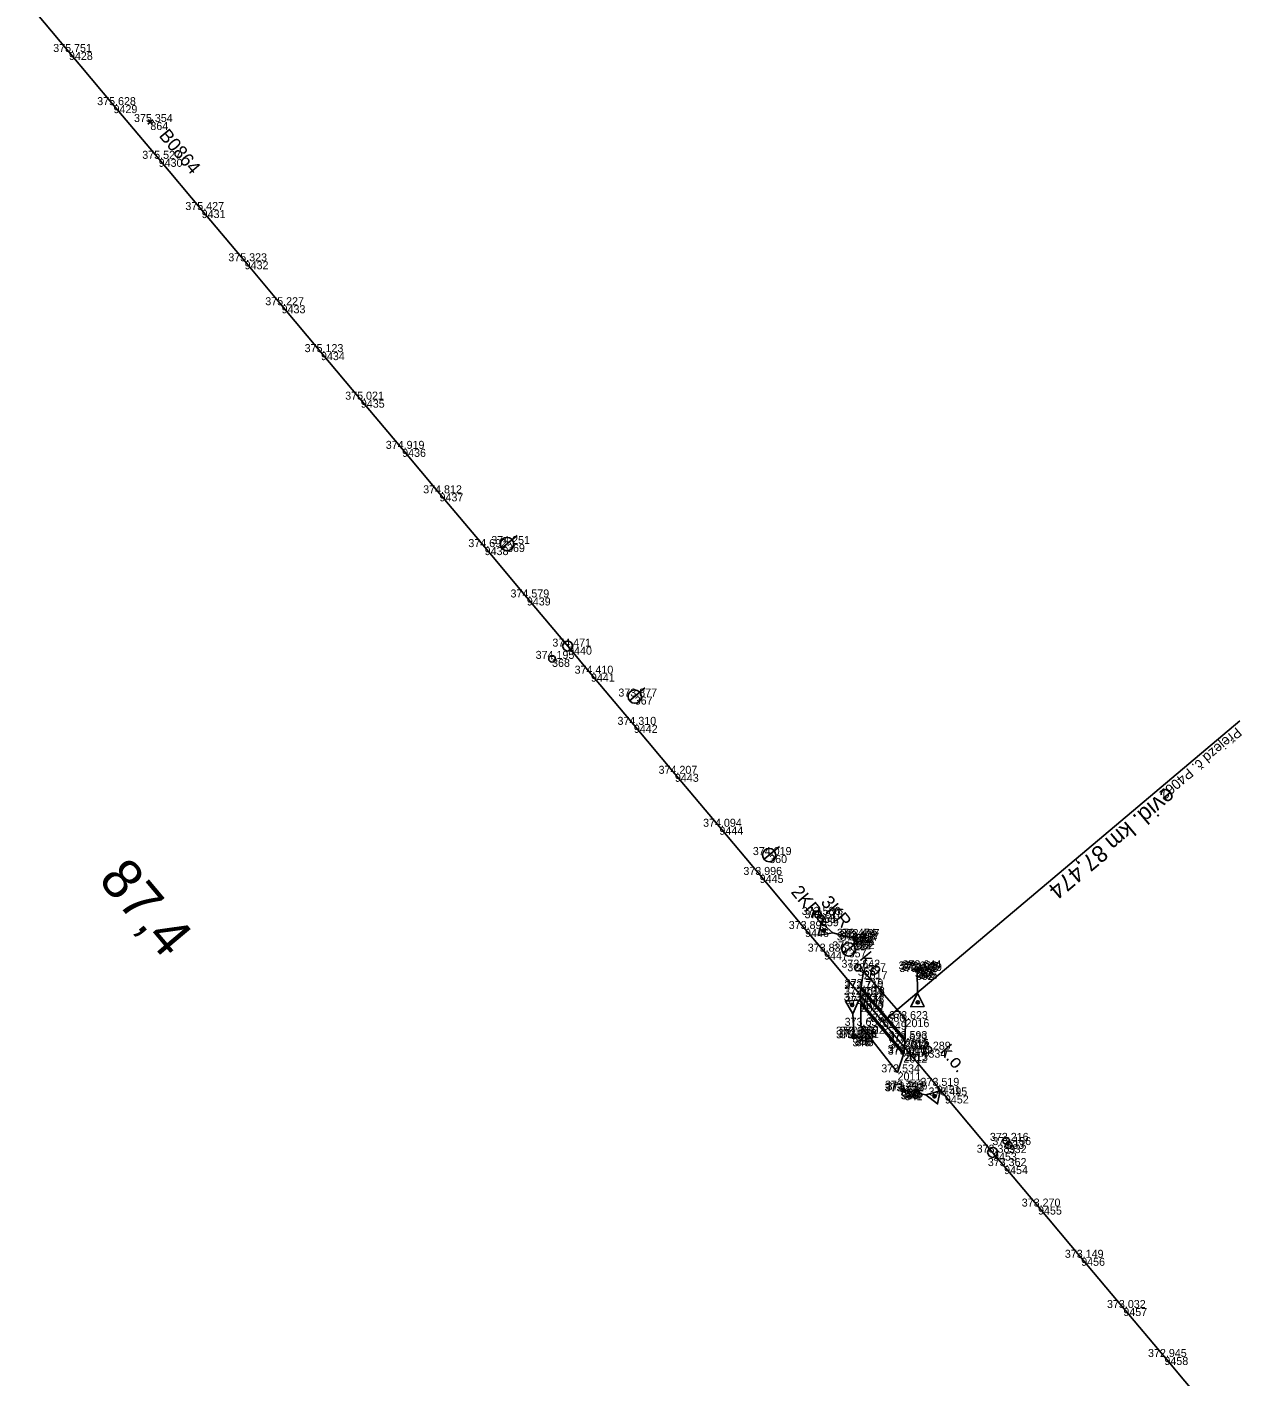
# Model space of a CAD drawing. Extents: x -599511 to -595511, y -1067427 to -1062061.
# Drawn here: x -596648.2 to -596466.1, y -1065676.3 to -1065474 of the extents above; entities that cross this region are included whole.
import ezdxf

# ---------------------------------------------------------------- set-up
doc = ezdxf.new("R2010")
doc.units = 0
for name, color, linetype in [('Vrstva 1', 7, 'Continuous'), ('Vrstva 12', 7, 'Continuous'), ('Vrstva 27', 7, 'Continuous'), ('Vrstva 4', 7, 'Continuous'), ('Vrstva 43', 7, 'Continuous'), ('Vrstva 50', 7, 'Continuous'), ('Vrstva 60', 7, 'Continuous'), ('Vrstva 61', 7, 'Continuous'), ('Vrstva 7', 7, 'Continuous')]:
    doc.layers.add(name, color=color, linetype=linetype)

msp = doc.modelspace()

# ---------------------------------------------------------------- linework, layer by layer
at = {"layer": 'Vrstva 1'}
msp.add_lwpolyline([(-596648.21, -1065470.29), (-596641.92, -1065477.78), (-596635.24, -1065485.75), (-596628.47, -1065493.8), (-596622.02, -1065501.48), (-596615.58, -1065509.16), (-596610.04, -1065515.75), (-596604.14, -1065522.78), (-596598.16, -1065529.91), (-596591.97, -1065537.28), (-596586.37, -1065543.95), (-596579.6, -1065552.01), (-596573.28, -1065559.56), (-596567.09, -1065566.93), (-596563.67, -1065570.99), (-596557.24, -1065578.66), (-596551.08, -1065586), (-596544.41, -1065593.94), (-596538.37, -1065601.16), (-596531.57, -1065609.27), (-596528.72, -1065612.66), (-596523.26, -1065619.18), (-596519.9, -1065623.17), (-596516.48, -1065627.21), (-596511.81, -1065632.78), (-596510.61, -1065634.22), (-596503.4, -1065642.8), (-596501.73, -1065644.81), (-596496.64, -1065650.88), (-596490.18, -1065658.56), (-596483.86, -1065666.09), (-596477.7, -1065673.43), (-596471.6, -1065680.69)], dxfattribs=at)
at = {"layer": 'Vrstva 12'}
for p, q in [((-596524.48, -1065625.11), (-596524.48, -1065625.11)), ((-596524.48, -1065625.65), (-596524.48, -1065625.65)), ((-596517.14, -1065633.2), (-596517.14, -1065633.2)), ((-596517.21, -1065633.58), (-596517.22, -1065633.59)), ((-596516.63, -1065633.73), (-596516.63, -1065633.73)), ((-596516.55, -1065633.33), (-596516.55, -1065633.33))]:
    msp.add_line(p, q, dxfattribs=at)
for points in [[(-596524.34, -1065610.43), (-596524.36, -1065610.97), (-596523.83, -1065611.03), (-596523.78, -1065610.48)], [(-596515.1, -1065615.33), (-596514.51, -1065615.16), (-596514.39, -1065615.56), (-596514.99, -1065615.71)], [(-596523.93, -1065625.1), (-596523.97, -1065625.63), (-596524.48, -1065625.65), (-596524.48, -1065625.11)], [(-596517.22, -1065633.59), (-596517.14, -1065633.2), (-596516.55, -1065633.33), (-596516.63, -1065633.73)], [(-596517.21, -1065633.58), (-596517.14, -1065633.2), (-596516.55, -1065633.33), (-596516.63, -1065633.73)]]:
    msp.add_lwpolyline(points, close=True, dxfattribs=at)
msp.add_lwpolyline([(-596523.97, -1065625.63), (-596524.48, -1065625.65), (-596524.48, -1065625.11), (-596523.93, -1065625.1)], dxfattribs=at)
at = {"layer": 'Vrstva 27'}
for p, q in [((-596529.65, -1065607.11), (-596529.59, -1065607.19)), ((-596529.23, -1065607.62), (-596529.17, -1065607.69)), ((-596523.71, -1065615.02), (-596523.64, -1065615.09)), ((-596513.12, -1065627.32), (-596513.05, -1065627.4))]:
    msp.add_line(p, q, dxfattribs=at)
for centre in [(-596529.62, -1065607.15), (-596529.2, -1065607.65), (-596523.67, -1065615.06), (-596513.08, -1065627.36)]:
    msp.add_circle(centre, 0.5, dxfattribs=at)
at = {"layer": 'Vrstva 4'}
for p, q in [((-596519.9, -1065623.17), (-596466.39, -1065578.04)), ((-596528.63, -1065609.71), (-596528.87, -1065609.29)), ((-596524.27, -1065611.48), (-596523.86, -1065609.98)), ((-596513.99, -1065615.41), (-596515.55, -1065615.43)), ((-596524.69, -1065620.82), (-596524.36, -1065620.46)), ((-596514.51, -1065620.09), (-596514.86, -1065620.43)), ((-596524.96, -1065625.52), (-596523.41, -1065625.42)), ((-596516.75, -1065632.68), (-596517.05, -1065634.2)), ((-596512.28, -1065634.14), (-596512.01, -1065634.55))]:
    msp.add_line(p, q, dxfattribs=at)
for points in [[(-596524.07, -1065610.73), (-596527.43, -1065609.83), (-596529.62, -1065610.26), (-596529.11, -1065608.33), (-596527.43, -1065609.83)], [(-596514.77, -1065615.42), (-596514.73, -1065618.9), (-596513.72, -1065620.89), (-596515.72, -1065620.92), (-596514.73, -1065618.9)], [(-596524.19, -1065625.47), (-596524.41, -1065622), (-596525.52, -1065620.06), (-596523.53, -1065619.93), (-596524.41, -1065622)], [(-596516.9, -1065633.44), (-596513.49, -1065634.11), (-596511.33, -1065633.53), (-596511.71, -1065635.49), (-596513.49, -1065634.11)]]:
    msp.add_lwpolyline(points, dxfattribs=at)
for points in [[(-596522.79, -1065615.6), (-596523.18, -1065617.97), (-596516.59, -1065625.78), (-596516.51, -1065622.78)], [(-596523.22, -1065618.28), (-596523.34, -1065620.02), (-596516.72, -1065627.85), (-596516.63, -1065626.1)], [(-596523.23, -1065620.52), (-596523.19, -1065623.78), (-596517.7, -1065630.76), (-596516.83, -1065628.1)]]:
    msp.add_lwpolyline(points, close=True, dxfattribs=at)
for centre in [(-596528.75, -1065609.5), (-596524.52, -1065620.64), (-596514.68, -1065620.26), (-596512.15, -1065634.35)]:
    msp.add_circle(centre, 0.248, dxfattribs=at)
at = {"layer": 'Vrstva 43'}
for p, q in [((-596574.72, -1065550.27), (-596577.02, -1065552.19)), ((-596555.58, -1065573.13), (-596557.87, -1065575.06)), ((-596535.41, -1065596.89), (-596537.71, -1065598.82)), ((-596523.51, -1065611.04), (-596525.81, -1065612.96))]:
    msp.add_line(p, q, dxfattribs=at)
for centre in [(-596576.25, -1065551.55), (-596557.11, -1065574.42), (-596536.95, -1065598.18), (-596525.04, -1065612.32)]:
    msp.add_circle(centre, 0.996, dxfattribs=at)
at = {"layer": 'Vrstva 50'}
msp.add_line((-596501.07, -1065641.62), (-596501.01, -1065641.7), dxfattribs=at)
msp.add_circle((-596501.04, -1065641.66), 0.5, dxfattribs=at)
at = {"layer": 'Vrstva 60'}
for p, q in [((-596641.92, -1065477.78), (-596641.92, -1065477.78)), ((-596635.24, -1065485.75), (-596635.24, -1065485.75)), ((-596629.72, -1065488.28), (-596629.72, -1065488.28)), ((-596628.47, -1065493.8), (-596628.47, -1065493.8)), ((-596622.02, -1065501.48), (-596622.02, -1065501.48)), ((-596615.58, -1065509.16), (-596615.58, -1065509.16)), ((-596610.04, -1065515.75), (-596610.04, -1065515.75)), ((-596604.14, -1065522.78), (-596604.14, -1065522.78)), ((-596598.16, -1065529.91), (-596598.16, -1065529.91)), ((-596591.97, -1065537.28), (-596591.97, -1065537.28)), ((-596586.37, -1065543.95), (-596586.37, -1065543.95)), ((-596579.6, -1065552.01), (-596579.6, -1065552.01)), ((-596576.25, -1065551.55), (-596576.25, -1065551.55)), ((-596573.28, -1065559.56), (-596573.28, -1065559.56)), ((-596567.09, -1065566.93), (-596567.09, -1065566.93)), ((-596569.5, -1065568.77), (-596569.5, -1065568.77)), ((-596563.67, -1065570.99), (-596563.67, -1065570.99)), ((-596557.11, -1065574.42), (-596557.11, -1065574.42)), ((-596557.24, -1065578.66), (-596557.24, -1065578.66)), ((-596551.08, -1065586), (-596551.08, -1065586)), ((-596544.41, -1065593.94), (-596544.41, -1065593.94)), ((-596536.95, -1065598.18), (-596536.95, -1065598.18)), ((-596538.37, -1065601.16), (-596538.37, -1065601.16)), ((-596529.62, -1065607.15), (-596529.62, -1065607.15)), ((-596529.2, -1065607.65), (-596529.2, -1065607.65)), ((-596531.57, -1065609.27), (-596531.57, -1065609.27)), ((-596524.34, -1065610.43), (-596524.34, -1065610.43)), ((-596524.07, -1065610.73), (-596524.07, -1065610.73)), ((-596523.78, -1065610.48), (-596523.78, -1065610.48)), ((-596528.72, -1065612.66), (-596528.72, -1065612.66)), ((-596525.04, -1065612.32), (-596525.04, -1065612.32)), ((-596524.36, -1065610.97), (-596524.36, -1065610.97)), ((-596523.83, -1065611.03), (-596523.83, -1065611.03)), ((-596523.67, -1065615.06), (-596523.67, -1065615.06)), ((-596522.79, -1065615.6), (-596522.79, -1065615.6)), ((-596515.1, -1065615.33), (-596515.1, -1065615.33)), ((-596514.99, -1065615.71), (-596514.99, -1065615.71)), ((-596514.77, -1065615.42), (-596514.77, -1065615.42)), ((-596514.51, -1065615.16), (-596514.51, -1065615.16)), ((-596514.39, -1065615.56), (-596514.39, -1065615.56)), ((-596523.22, -1065618.28), (-596523.22, -1065618.28)), ((-596523.18, -1065617.97), (-596523.18, -1065617.97)), ((-596523.34, -1065620.02), (-596523.34, -1065620.02)), ((-596523.26, -1065619.18), (-596523.26, -1065619.18)), ((-596523.23, -1065620.52), (-596523.23, -1065620.52)), ((-596516.51, -1065622.78), (-596516.51, -1065622.78)), ((-596524.48, -1065625.11), (-596524.48, -1065625.11)), ((-596524.48, -1065625.11), (-596524.48, -1065625.11)), ((-596523.93, -1065625.1), (-596523.93, -1065625.1)), ((-596523.19, -1065623.78), (-596523.19, -1065623.78)), ((-596519.9, -1065623.17), (-596519.9, -1065623.17)), ((-596524.48, -1065625.65), (-596524.48, -1065625.65)), ((-596524.48, -1065625.65), (-596524.48, -1065625.65)), ((-596524.19, -1065625.47), (-596524.19, -1065625.47)), ((-596523.97, -1065625.63), (-596523.97, -1065625.63)), ((-596516.63, -1065626.1), (-596516.63, -1065626.1)), ((-596516.59, -1065625.78), (-596516.59, -1065625.78)), ((-596516.83, -1065628.1), (-596516.83, -1065628.1)), ((-596516.72, -1065627.85), (-596516.72, -1065627.85)), ((-596516.48, -1065627.21), (-596516.48, -1065627.21)), ((-596513.08, -1065627.36), (-596513.08, -1065627.36)), ((-596517.7, -1065630.76), (-596517.7, -1065630.76)), ((-596517.14, -1065633.2), (-596517.14, -1065633.2)), ((-596517.14, -1065633.2), (-596517.14, -1065633.2)), ((-596511.81, -1065632.78), (-596511.81, -1065632.78)), ((-596517.22, -1065633.59), (-596517.22, -1065633.59)), ((-596517.21, -1065633.58), (-596517.21, -1065633.58)), ((-596516.9, -1065633.44), (-596516.9, -1065633.44)), ((-596516.63, -1065633.73), (-596516.63, -1065633.73)), ((-596516.63, -1065633.73), (-596516.63, -1065633.73)), ((-596516.55, -1065633.33), (-596516.55, -1065633.33)), ((-596516.55, -1065633.33), (-596516.55, -1065633.33)), ((-596510.61, -1065634.22), (-596510.61, -1065634.22)), ((-596501.41, -1065641.03), (-596501.41, -1065641.03)), ((-596503.4, -1065642.8), (-596503.4, -1065642.8)), ((-596501.04, -1065641.66), (-596501.04, -1065641.66)), ((-596501.73, -1065644.81), (-596501.73, -1065644.81)), ((-596496.64, -1065650.88), (-596496.64, -1065650.88)), ((-596490.18, -1065658.56), (-596490.18, -1065658.56)), ((-596483.86, -1065666.09), (-596483.86, -1065666.09)), ((-596477.7, -1065673.43), (-596477.7, -1065673.43))]:
    msp.add_line(p, q, dxfattribs=at)
at = {"layer": 'Vrstva 7'}
for p, q in [((-596629.34, -1065487.96), (-596630.1, -1065488.6)), ((-596630.04, -1065487.9), (-596629.4, -1065488.66)), ((-596569.54, -1065568.73), (-596569.47, -1065568.81)), ((-596501.44, -1065640.99), (-596501.38, -1065641.07))]:
    msp.add_line(p, q, dxfattribs=at)
for centre, radius in [((-596567.16, -1065566.84), 0.75), ((-596569.5, -1065568.77), 0.5), ((-596501.41, -1065641.03), 0.5), ((-596503.45, -1065642.75), 0.75)]:
    msp.add_circle(centre, radius, dxfattribs=at)

# ---------------------------------------------------------------- texts
at = {"layer": 'Vrstva 27'}
for s, rotation, p in [('2KR', 309.9948, (-596533.79, -1065603.76)), ('3KR', 310.0311, (-596529.32, -1065605.31)), ('k.o.', 309.9366, (-596523.47, -1065613.76)), ('k.o.', 309.9791, (-596511.42, -1065627.66))]:
    msp.add_text(s, height=2, rotation=rotation, dxfattribs=at).set_placement(p)
at = {"layer": 'Vrstva 4'}
for s, height, p in [('Přejezd č. P4062', 1.5, (-596466.91, -1065578.94)), ('evid. km 87,474', 2.5, (-596477.27, -1065587.84))]:
    msp.add_text(s, height=height, rotation=220.1449, dxfattribs=at).set_placement(p)
at = {"layer": 'Vrstva 60'}
for s, p in [('9428', (-596641.92, -1065478.98)), ('9429', (-596635.24, -1065486.95)), ('864', (-596629.72, -1065489.48)), ('9430', (-596628.47, -1065495)), ('9431', (-596622.02, -1065502.68)), ('9432', (-596615.58, -1065510.36)), ('9433', (-596610.04, -1065516.95)), ('9434', (-596604.14, -1065523.98)), ('9435', (-596598.16, -1065531.11)), ('9436', (-596591.97, -1065538.48)), ('9437', (-596586.37, -1065545.15)), ('9438', (-596579.6, -1065553.21)), ('369', (-596576.25, -1065552.75)), ('9439', (-596573.28, -1065560.76)), ('9440', (-596567.09, -1065568.13)), ('368', (-596569.5, -1065569.97)), ('9441', (-596563.67, -1065572.19)), ('367', (-596557.11, -1065575.62)), ('9442', (-596557.24, -1065579.86)), ('9443', (-596551.08, -1065587.2)), ('9444', (-596544.41, -1065595.14)), ('360', (-596536.95, -1065599.38)), ('9445', (-596538.37, -1065602.36)), ('358', (-596529.62, -1065608.35)), ('359', (-596529.2, -1065608.85)), ('9446', (-596531.57, -1065610.47)), ('353', (-596524.36, -1065612.17)), ('354', (-596524.34, -1065611.63)), ('355', (-596524.07, -1065611.93)), ('351', (-596523.78, -1065611.68)), ('9447', (-596528.72, -1065613.85)), ('357', (-596525.04, -1065613.52)), ('352', (-596523.83, -1065612.23)), ('356', (-596523.67, -1065616.26)), ('2017', (-596522.79, -1065616.8)), ('363', (-596515.1, -1065616.53)), ('362', (-596514.99, -1065616.91)), ('366', (-596514.77, -1065616.62)), ('364', (-596514.51, -1065616.36)), ('365', (-596514.39, -1065616.77)), ('2019', (-596523.22, -1065619.48)), ('2018', (-596523.18, -1065619.17)), ('2020', (-596523.34, -1065621.22)), ('9448', (-596523.26, -1065620.38)), ('2021', (-596523.23, -1065621.72)), ('2016', (-596516.51, -1065623.98)), ('348', (-596524.48, -1065626.31)), ('349', (-596524.48, -1065626.31)), ('344', (-596523.93, -1065626.3)), ('2022', (-596523.19, -1065624.98)), ('9449', (-596519.9, -1065624.37)), ('346', (-596524.48, -1065626.85)), ('347', (-596524.48, -1065626.85)), ('350', (-596524.19, -1065626.67)), ('345', (-596523.97, -1065626.83)), ('2014', (-596516.63, -1065627.3)), ('2015', (-596516.59, -1065626.98)), ('2012', (-596516.83, -1065629.3)), ('2013', (-596516.72, -1065629.05)), ('9450', (-596516.48, -1065628.41)), ('334', (-596513.08, -1065628.56)), ('2011', (-596517.7, -1065631.96)), ('337', (-596517.14, -1065634.4)), ('338', (-596517.14, -1065634.4)), ('9451', (-596511.81, -1065633.98)), ('340', (-596517.22, -1065634.79)), ('339', (-596517.21, -1065634.78)), ('343', (-596516.9, -1065634.64)), ('341', (-596516.63, -1065634.93)), ('342', (-596516.63, -1065634.93)), ('336', (-596516.55, -1065634.53)), ('335', (-596516.55, -1065634.53)), ('9452', (-596510.61, -1065635.42)), ('333', (-596501.41, -1065642.23)), ('9453', (-596503.4, -1065644)), ('332', (-596501.04, -1065642.86)), ('9454', (-596501.73, -1065646.01)), ('9455', (-596496.64, -1065652.08)), ('9456', (-596490.18, -1065659.76)), ('9457', (-596483.86, -1065667.29)), ('9458', (-596477.7, -1065674.63))]:
    msp.add_text(s, height=1.2, dxfattribs=at).set_placement(p)
at = {"layer": 'Vrstva 61'}
for s, p in [('375.751', (-596644.28, -1065477.78)), ('375.628', (-596637.69, -1065485.75)), ('375.354', (-596632.17, -1065488.28)), ('375.527', (-596630.93, -1065493.8)), ('375.427', (-596624.47, -1065501.48)), ('375.323', (-596618.03, -1065509.16)), ('375.227', (-596612.49, -1065515.75)), ('375.123', (-596606.59, -1065522.78)), ('375.021', (-596600.51, -1065529.91)), ('374.919', (-596594.43, -1065537.28)), ('374.812', (-596588.82, -1065543.95)), ('374.692', (-596582.05, -1065552.01)), ('374.251', (-596578.61, -1065551.55)), ('374.579', (-596575.73, -1065559.56)), ('374.471', (-596569.45, -1065566.93)), ('374.195', (-596571.96, -1065568.77)), ('374.410', (-596566.12, -1065570.99)), ('373.877', (-596559.56, -1065574.42)), ('374.310', (-596559.69, -1065578.66)), ('374.207', (-596553.53, -1065586)), ('374.094', (-596546.86, -1065593.94)), ('374.019', (-596539.4, -1065598.18)), ('373.996', (-596540.82, -1065601.16)), ('373.586', (-596532.07, -1065607.15)), ('373.578', (-596531.65, -1065607.65)), ('373.895', (-596534.02, -1065609.27)), ('373.468', (-596526.81, -1065610.97)), ('373.474', (-596526.79, -1065610.43)), ('373.472', (-596526.52, -1065610.73)), ('373.467', (-596526.28, -1065611.03)), ('373.487', (-596526.23, -1065610.48)), ('373.836', (-596531.17, -1065612.66)), ('373.222', (-596527.49, -1065612.32)), ('373.642', (-596526.12, -1065615.06)), ('373.567', (-596525.24, -1065615.6)), ('373.638', (-596517.56, -1065615.33)), ('373.646', (-596517.44, -1065615.71)), ('373.645', (-596517.22, -1065615.42)), ('373.644', (-596516.96, -1065615.16)), ('373.639', (-596516.85, -1065615.56)), ('373.719', (-596525.63, -1065617.97)), ('373.732', (-596525.79, -1065620.02)), ('373.734', (-596525.71, -1065619.18)), ('373.740', (-596525.68, -1065618.28)), ('373.671', (-596525.59, -1065620.52)), ('373.652', (-596525.64, -1065623.78)), ('373.680', (-596522.35, -1065623.17)), ('373.623', (-596518.96, -1065622.78)), ('373.128', (-596526.93, -1065625.11)), ('373.627', (-596526.93, -1065625.11)), ('373.624', (-596526.93, -1065625.65)), ('373.124', (-596526.93, -1065625.65)), ('373.656', (-596526.64, -1065625.47)), ('373.650', (-596526.38, -1065625.1)), ('373.611', (-596526.33, -1065625.63)), ('373.629', (-596519.08, -1065626.1)), ('373.593', (-596519.04, -1065625.78)), ('373.611', (-596519.18, -1065628.1)), ('373.618', (-596519.18, -1065627.85)), ('373.617', (-596518.93, -1065627.21)), ('373.289', (-596515.54, -1065627.36)), ('373.534', (-596520.15, -1065630.76)), ('373.752', (-596519.66, -1065633.58)), ('373.443', (-596519.59, -1065633.2)), ('373.743', (-596519.59, -1065633.2)), ('373.451', (-596519.58, -1065633.59)), ('373.743', (-596519.35, -1065633.44)), ('373.449', (-596519.09, -1065633.73)), ('373.749', (-596519.08, -1065633.73)), ('373.746', (-596519, -1065633.33)), ('373.447', (-596519, -1065633.33)), ('373.519', (-596514.26, -1065632.78)), ('373.495', (-596513.06, -1065634.22)), ('373.216', (-596503.86, -1065641.03)), ('373.156', (-596503.49, -1065641.66)), ('373.389', (-596505.85, -1065642.8)), ('373.362', (-596504.18, -1065644.81)), ('373.270', (-596499.09, -1065650.88)), ('373.149', (-596492.63, -1065658.56)), ('373.032', (-596486.31, -1065666.09)), ('372.945', (-596480.16, -1065673.43))]:
    msp.add_text(s, height=1.2, dxfattribs=at).set_placement(p)
at = {"layer": 'Vrstva 7'}
for s, height, rotation, p in [('B0864', 2, 310.0323, (-596628.53, -1065490.37)), ('87,4', 6, 310.0252, (-596637.66, -1065601.95))]:
    msp.add_text(s, height=height, rotation=rotation, dxfattribs=at).set_placement(p)

doc.saveas('drawing.dxf')
